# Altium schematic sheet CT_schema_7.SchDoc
size 287 x 160 mm
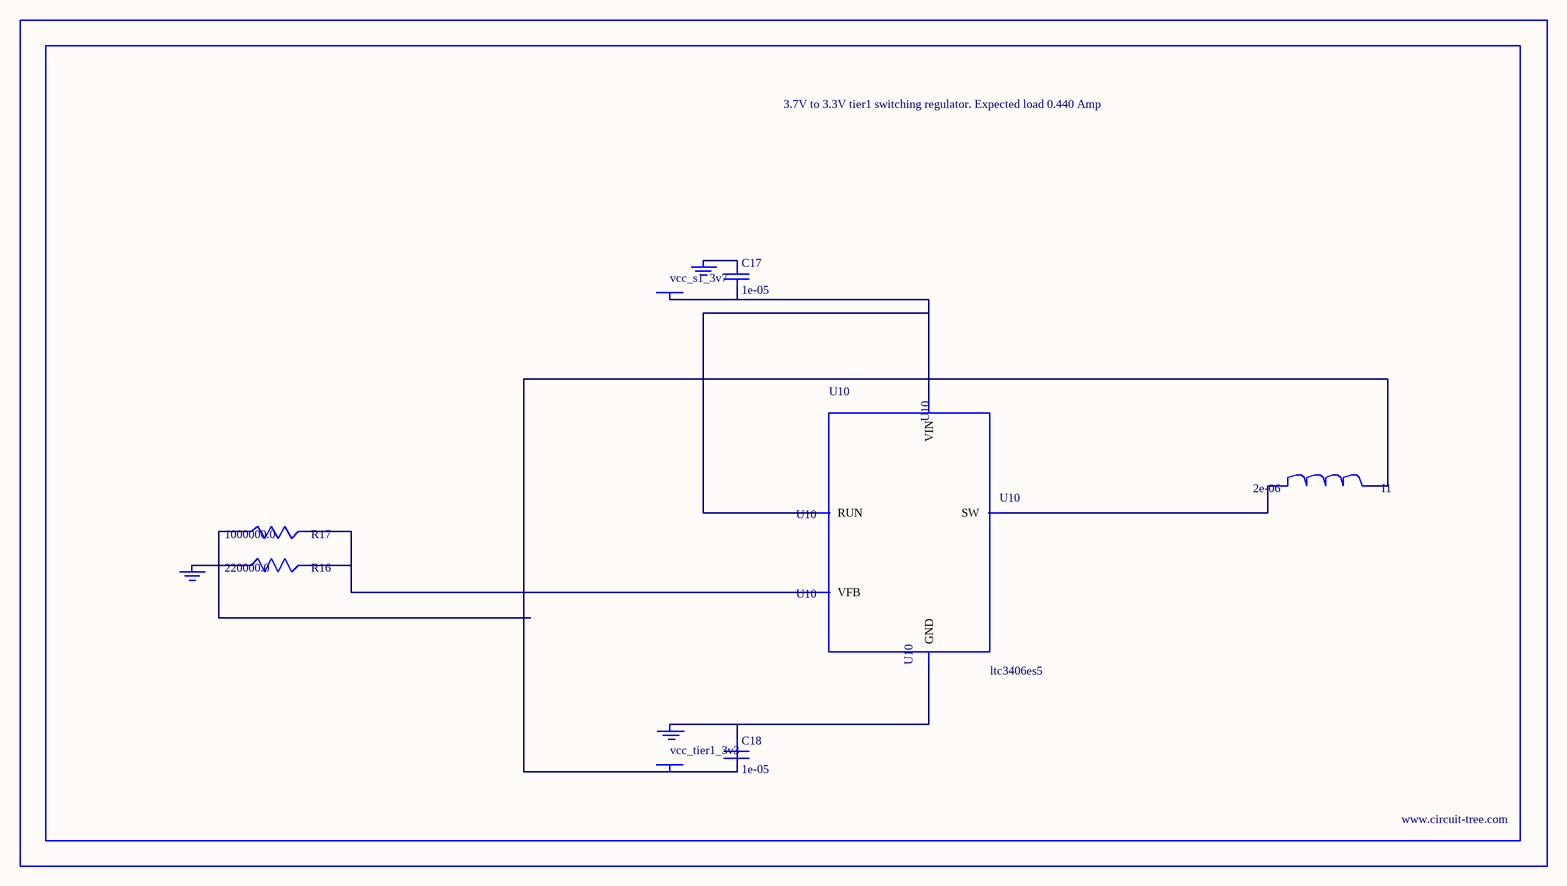
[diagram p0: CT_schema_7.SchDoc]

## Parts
BORDER6  (no value)
C17  1e-05  [C0805]
C18  1e-05  [C0805]
GND_INSTANCE_6_0  (no value)
GND_INSTANCE_6_1  (no value)
GND_INSTANCE_6_2  (no value)
I1  2e-06  [WE-HCI_7030/7040/7050]
POWER_INSTANCE_6_0  vcc_tier1_3v3
POWER_INSTANCE_6_1  vcc_s1_3v7
R16  220000.0  [R0603]
R17  1000000.0  [R0603]
U10  ltc3406es5  [TSOT-23-5]

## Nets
NetC17_1: C17.1 GND_INSTANCE_6_1.0(GND)
NetC17_2: C17.2 POWER_INSTANCE_6_1.0(PWR) U10.1(RUN) U10.4(VIN)
NetC18_1: C18.1 GND_INSTANCE_6_0.0(GND) U10.2(GND)
NetC18_2: C18.2 I1.2 POWER_INSTANCE_6_0.0(PWR) R17.1
NetGND_INSTANCE_6_2_0: GND_INSTANCE_6_2.0(GND) R16.1
NetI1_1: I1.1 U10.3(SW)
NetR16_2: R16.2 R17.2 U10.5(VFB)

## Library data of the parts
BORDER6 = BORDER_PAGE6
C17 C18 = C0805C106K8RACTU
GND_INSTANCE_6_0-GND_INSTANCE_6_2 = GND
I1 = 744314200
POWER_INSTANCE_6_0 POWER_INSTANCE_6_1 = PWR
R16 = RC0603JR-07220KL
R17 = RC0603JR-071ML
